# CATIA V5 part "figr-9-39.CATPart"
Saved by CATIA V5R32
Part number: Part1
Bounding box of the stored display mesh (mm): x -40 to 40, y -20 to 191.034, z 0 to 131.022
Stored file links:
  D:\PROJECTS\Project 2022\CATIA V5 6R 2022\Resources\Part Files\c09_catia_v5_6r2022_prt\c09_catia_v5_6r2022_prt\figr-9-39.CATPart
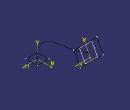
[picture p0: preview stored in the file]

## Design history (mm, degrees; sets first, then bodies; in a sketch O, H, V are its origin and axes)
Set1
  Plane1: type Normal, Curve Sketch2, RefPoint vertex of Sketch2
Body1 (main body)
  Sketch1 on xy-plane, origin (0, 0, 0), H (1, 0, 0), V (0, 1, 0)
    line L1 (20, 20) -> (20, -20)
    line L2 (20, -20) -> (-20, -20)
    line L3 (-20, -20) -> (-20, 20)
    line L4 (-20, 20) -> (20, 20)
    vertical: L1 V, L3 V
    horizontal: L2 H, L4 H
    equidistance: L1 L3 O, L2 L4 O
  Sketch2 on yz-plane, origin (0, 0, 0), H (0, 1, 0), V (0, 0, 1)
    spline S1 through (0, 0) (20, 60) (60, 80) (120, 90) (180, 110)
    point P1 (0, 0)
    coincidence: P1 O
  Sketch3 on Plane1, origin (0, 186.3865, 97.8327), H (1, 0, 0), V (0, -0.4648, 0.8854)
    point P1 (0, 13.7415)
    line L1 (40, 37.4831) -> (40, -10)
    line L2 (40, -10) -> (-40, -10)
    line L3 (-40, -10) -> (-40, 37.4831)
    line L4 (-40, 37.4831) -> (40, 37.4831)
    reference projected point E1 (0, 13.7415) from vertex of Sketch2
    coincidence: P1 V, P1 E1
    vertical: L1 V, L3 V
    horizontal: L2 H, L4 H
    equidistance: L1 L3 P1, L2 L4 P1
